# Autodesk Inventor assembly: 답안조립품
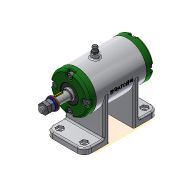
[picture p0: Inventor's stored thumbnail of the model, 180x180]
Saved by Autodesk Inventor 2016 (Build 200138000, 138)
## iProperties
Created: 2017-02
Part Number: 답안조립품
Material: 일반
Document SubType Name: Assembly
Designer: H
Author: H
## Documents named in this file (16)
- C:\Users\CAMTIC\Desktop\470207V1011\답안조립품.iam
- C:\Users\CAMTIC\Desktop\470207V1011\V벨트풀리.ipt
- C:\Users\CAMTIC\Desktop\470207V1011\너트 M 8.ipt
- C:\Users\CAMTIC\Desktop\470207V1011\니플 M 6 x 0.75.ipt
- C:\Users\CAMTIC\Desktop\470207V1011\뒤커버.ipt
- C:\Users\CAMTIC\Desktop\470207V1011\베어링 15 x 32 x 9.ipt
- C:\Users\CAMTIC\Desktop\470207V1011\본체.ipt
- C:\Users\CAMTIC\Desktop\470207V1011\볼트 M 6 x 8.ipt
- C:\Users\CAMTIC\Desktop\470207V1011\볼트 M4 x 12.ipt
- C:\Users\CAMTIC\Desktop\470207V1011\스프링와셔 8.ipt
- C:\Users\CAMTIC\Desktop\470207V1011\앞커버.ipt
- C:\Users\CAMTIC\Desktop\470207V1011\오일 실 15 25 7.ipt
- C:\Users\CAMTIC\Desktop\470207V1011\와셔 6x11.5.ipt
- C:\Users\CAMTIC\Desktop\470207V1011\와셔 8x17.ipt
- C:\Users\CAMTIC\Desktop\470207V1011\축.ipt
- C:\Users\CAMTIC\Desktop\470207V1011\키 3 x 3 x 12.ipt
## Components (11 placed, 3 different names)
1. V벨트풀리:1
2. KS B 2023 6002 - 15 x 32 x 9:1
3. KS B 2023 6002 - 15 x 32 x 9:2
4. ISO 4762 M4 x 12:1
5. ISO 4762 M4 x 12:3
6. ISO 4762 M4 x 12:4
7. ISO 4762 M4 x 12:5
8. ISO 4762 M4 x 12:2
9. ISO 4762 M4 x 12:6
10. ISO 4762 M4 x 12:7
11. ISO 4762 M4 x 12:8
